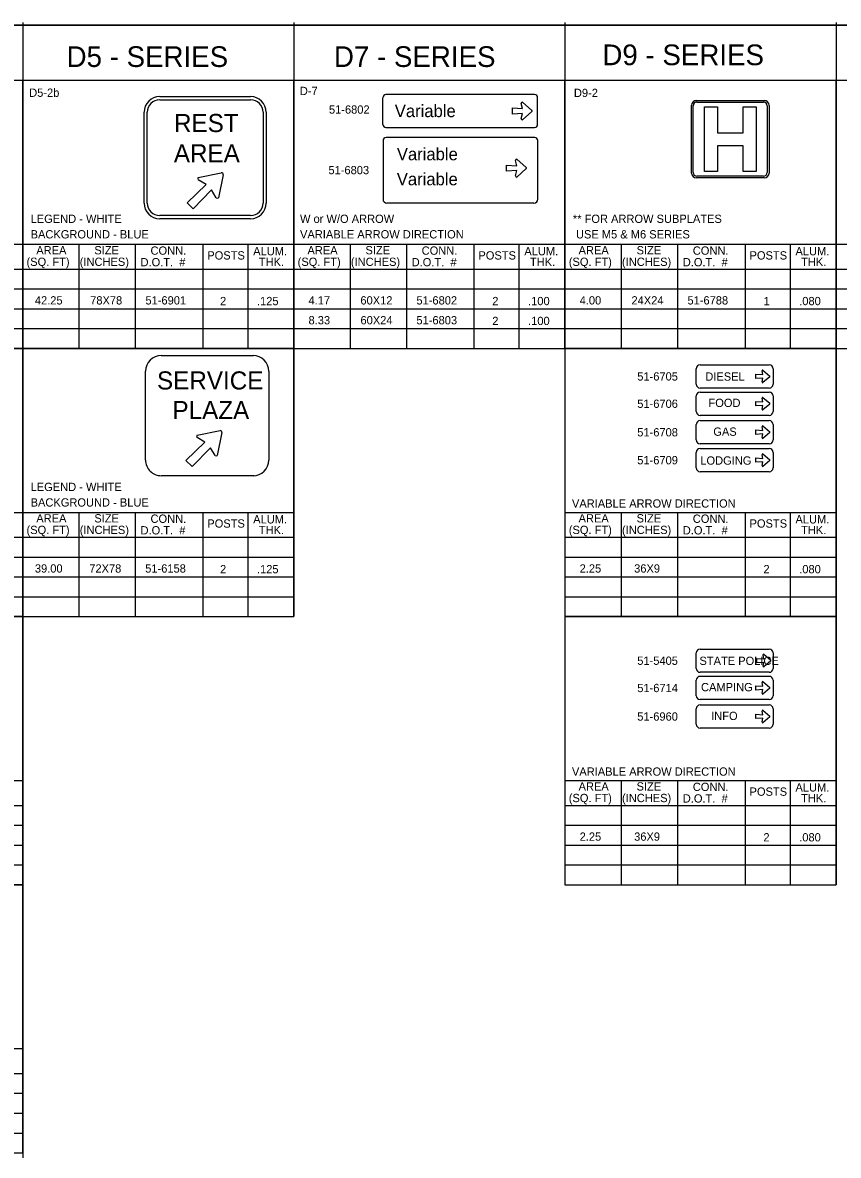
# Model space of a CAD drawing. Extents: x 0 to 2011, y -22 to 1183.
# Drawn here: x 424 to 739.2, y 392.2 to 830 of the extents above; entities that cross this region are included whole.
import ezdxf

# ---------------------------------------------------------------- set-up
doc = ezdxf.new("R2010")
doc.units = 0
for name, color, linetype in [('CT_Border_Perimeter_Shape', 7, 'Continuous'), ('CT_Construction', 7, 'Continuous'), ('Level 1', 7, 'Continuous'), ('Level 2', 7, 'Continuous'), ('Level 22', 7, 'Continuous'), ('Level 5', 7, 'Continuous')]:
    doc.layers.add(name, color=color, linetype=linetype)

msp = doc.modelspace()

# ---------------------------------------------------------------- linework, layer by layer
at = {"layer": 'CT_Border_Perimeter_Shape'}
msp.add_lwpolyline([(0, -0.97), (1270, -0.97), (1270, 829.03), (0, 829.03)], close=True, dxfattribs=at)
at = {"layer": 'CT_Construction'}
msp.add_lwpolyline([(0, 829.03), (1270, 829.03), (1270, 59.03), (0, 59.03)], close=True, dxfattribs=at)
at = {"layer": 'Level 1'}
for p, q in [((477.01, 801.4), (512.09, 801.4)), ((621.79, 802.19), (564.38, 802.19)), ((477.01, 800.19), (512.09, 800.19)), ((563.17, 790.7), (563.17, 800.98)), ((613.22, 794.68), (613.22, 797.08)), ((613.22, 797.08), (617.1, 796.82)), ((617.1, 796.82), (616.59, 798.81)), ((617.1, 799.32), (617.1, 799.32)), ((617.1, 799.32), (620.81, 796.07)), ((623, 790.7), (623, 800.98)), ((470.97, 760.28), (470.97, 795.35)), ((472.18, 760.28), (472.18, 795.35)), ((516.93, 795.35), (516.93, 760.28)), ((518.13, 795.35), (518.13, 760.28)), ((617.1, 794.93), (613.22, 794.68)), ((616.59, 792.94), (617.1, 794.93)), ((617.05, 795.88), (617.05, 795.88)), ((620.81, 795.69), (617.1, 792.43)), ((620.81, 795.69), (620.81, 795.69)), ((564.38, 789.5), (621.79, 789.5)), ((563.26, 784.43), (563.26, 761.76)), ((621.88, 785.64), (564.47, 785.64)), ((623.09, 761.76), (623.09, 784.43)), ((611.03, 772.58), (611.03, 774.98)), ((611.03, 774.98), (614.91, 774.72)), ((614.91, 774.72), (614.4, 776.71)), ((614.91, 777.22), (618.62, 773.97)), ((491.89, 770.15), (500.76, 771.93)), ((501.48, 771.21), (499.71, 762.34)), ((614.91, 772.84), (611.03, 772.58)), ((614.4, 770.85), (614.91, 772.84)), ((618.62, 773.59), (614.91, 770.34)), ((614.91, 773.06), (614.91, 773.06)), ((618.62, 773.59), (618.62, 773.59)), ((487.59, 760.38), (494.89, 767.5)), ((494.89, 767.5), (491.89, 769.29)), ((614.86, 769.61), (614.86, 769.61)), ((497.06, 765.33), (489.94, 758.04)), ((498.84, 762.34), (497.06, 765.33)), ((489.94, 758.04), (487.59, 760.38)), ((621.58, 760.25), (564.77, 760.25)), ((512.09, 755.44), (477.01, 755.44)), ((512.09, 754.23), (477.01, 754.23)), ((512.09, 754.23), (477.01, 754.23)), ((477.54, 701.33), (513.23, 701.33)), ((684.28, 690.28), (684.28, 696.26)), ((685.79, 697.77), (712.45, 697.77)), ((713.96, 696.26), (713.96, 690.28)), ((471.51, 660.95), (471.51, 695.31)), ((471.51, 695.31), (471.51, 695.29)), ((519.13, 695.25), (519.13, 660.95)), ((707.3, 692.45), (707.3, 694.15)), ((707.3, 694.15), (710.05, 693.97)), ((710.05, 692.63), (707.3, 692.45)), ((710.05, 693.97), (709.68, 695.38)), ((709.68, 691.22), (710.05, 692.63)), ((710.05, 695.74), (710.05, 695.74)), ((710.05, 695.74), (712.68, 693.43)), ((712.68, 693.16), (710.05, 690.86)), ((712.68, 693.16), (712.68, 693.16)), ((712.45, 688.77), (685.79, 688.77)), ((684.28, 679.73), (684.28, 685.71)), ((685.79, 687.22), (712.45, 687.22)), ((707.3, 681.9), (707.3, 683.59)), ((707.3, 683.59), (710.05, 683.41)), ((710.05, 683.41), (709.68, 684.82)), ((710.05, 685.19), (710.05, 685.19)), ((710.05, 685.19), (712.68, 682.88)), ((713.96, 685.71), (713.96, 679.73)), ((710.05, 682.08), (707.3, 681.9)), ((709.68, 680.67), (710.05, 682.08)), ((712.68, 682.61), (710.05, 680.3)), ((712.68, 682.61), (712.68, 682.61)), ((684.28, 668.71), (684.28, 674.68)), ((684.28, 668.71), (684.28, 674.68)), ((712.45, 678.22), (685.79, 678.22)), ((685.79, 676.2), (712.45, 676.2)), ((685.79, 676.2), (712.45, 676.2)), ((713.96, 674.68), (713.96, 668.71)), ((713.96, 674.68), (713.96, 668.71)), ((491.42, 670.54), (500.29, 672.31)), ((501.02, 671.59), (499.24, 662.72)), ((707.3, 670.87), (707.3, 672.57)), ((707.3, 672.57), (710.05, 672.39)), ((707.3, 670.87), (707.3, 672.57)), ((707.3, 672.57), (710.05, 672.39)), ((710.05, 671.05), (707.3, 670.87)), ((710.05, 671.05), (707.3, 670.87)), ((710.05, 672.39), (709.68, 673.8)), ((710.05, 672.39), (709.68, 673.8)), ((709.68, 669.64), (710.05, 671.05)), ((709.68, 669.64), (710.05, 671.05)), ((710.05, 674.16), (710.05, 674.16)), ((710.05, 674.16), (712.68, 671.86)), ((710.05, 674.16), (710.05, 674.16)), ((710.05, 674.16), (712.68, 671.86)), ((712.68, 671.59), (710.05, 669.28)), ((712.68, 671.59), (710.05, 669.28)), ((712.68, 671.59), (712.68, 671.59)), ((712.68, 671.59), (712.68, 671.59)), ((487.12, 660.77), (494.42, 667.89)), ((496.59, 665.72), (489.47, 658.42)), ((494.42, 667.89), (491.42, 669.67)), ((498.37, 662.72), (496.59, 665.72)), ((712.45, 667.2), (685.79, 667.2)), ((712.45, 667.2), (685.79, 667.2)), ((684.28, 657.92), (684.28, 663.9)), ((685.79, 665.41), (712.45, 665.41)), ((707.3, 660.09), (707.3, 661.79)), ((707.3, 661.79), (710.05, 661.6)), ((710.05, 661.6), (709.68, 663.02)), ((710.05, 663.38), (710.05, 663.38)), ((710.05, 663.38), (712.68, 661.07)), ((713.96, 663.9), (713.96, 657.92)), ((489.47, 658.42), (487.12, 660.77)), ((710.05, 660.27), (707.3, 660.09)), ((709.68, 658.86), (710.05, 660.27)), ((712.68, 660.8), (710.05, 658.49)), ((712.68, 660.8), (712.68, 660.8)), ((513.49, 654.91), (477.63, 654.91)), ((513.08, 654.91), (477.63, 654.91)), ((712.45, 656.41), (685.79, 656.41)), ((685.79, 587.91), (712.45, 587.91)), ((684.28, 580.42), (684.28, 586.4)), ((707.67, 582.58), (707.67, 584.28)), ((707.67, 584.28), (710.42, 584.1)), ((710.42, 582.77), (707.67, 582.58)), ((710.05, 585.87), (710.05, 585.87)), ((710.42, 584.1), (710.06, 585.51)), ((710.06, 581.35), (710.42, 582.77)), ((710.42, 585.87), (713.05, 583.57)), ((713.05, 583.3), (710.42, 580.99)), ((713.05, 583.3), (713.05, 583.3)), ((713.96, 586.4), (713.96, 580.42)), ((712.45, 578.91), (685.79, 578.91)), ((684.28, 569.87), (684.28, 575.84)), ((685.79, 577.36), (712.45, 577.36)), ((707.3, 572.03), (707.3, 573.73)), ((707.3, 573.73), (710.05, 573.55)), ((710.05, 573.55), (709.68, 574.96)), ((710.05, 575.32), (710.05, 575.32)), ((710.05, 575.32), (712.68, 573.02)), ((713.96, 575.84), (713.96, 569.87)), ((710.05, 572.21), (707.3, 572.03)), ((709.68, 570.8), (710.05, 572.21)), ((712.68, 572.75), (710.05, 570.44)), ((712.68, 572.75), (712.68, 572.75)), ((684.28, 558.85), (684.28, 564.82)), ((684.28, 558.85), (684.28, 564.82)), ((712.45, 568.36), (685.79, 568.36)), ((685.79, 566.33), (712.45, 566.33)), ((685.79, 566.33), (712.45, 566.33)), ((713.96, 564.82), (713.96, 558.85)), ((713.96, 564.82), (713.96, 558.85)), ((707.3, 561.01), (707.3, 562.71)), ((707.3, 562.71), (710.05, 562.53)), ((707.3, 561.01), (707.3, 562.71)), ((707.3, 562.71), (710.05, 562.53)), ((710.05, 561.19), (707.3, 561.01)), ((710.05, 561.19), (707.3, 561.01)), ((710.05, 562.53), (709.68, 563.94)), ((710.05, 562.53), (709.68, 563.94)), ((709.68, 559.78), (710.05, 561.19)), ((709.68, 559.78), (710.05, 561.19)), ((710.05, 564.3), (710.05, 564.3)), ((710.05, 564.3), (712.68, 562)), ((710.05, 564.3), (710.05, 564.3)), ((710.05, 564.3), (712.68, 562)), ((712.68, 561.72), (710.05, 559.42)), ((712.68, 561.72), (710.05, 559.42)), ((712.68, 561.72), (712.68, 561.72)), ((712.68, 561.72), (712.68, 561.72)), ((712.45, 557.34), (685.79, 557.34)), ((712.45, 557.34), (685.79, 557.34))]:
    msp.add_line(p, q, dxfattribs=at)
for centre, radius, start, end in [((477.01, 795.35), 6.05, 90, 180), ((512.09, 795.35), 6.05, 0, 90), ((564.38, 800.98), 1.21, 90, 180), ((621.79, 800.98), 1.21, 360, 90), ((477.01, 795.35), 4.84, 90, 180), ((512.09, 795.35), 4.84, 0, 90), ((617.1, 798.81), 0.51, 90, 180), ((617.1, 792.94), 0.51, 180, 270), ((620.64, 795.88), 0.255, 311.213, 48.6399), ((564.38, 790.7), 1.21, 180, 270), ((621.79, 790.7), 1.21, 270, 0), ((564.47, 784.43), 1.21, 90, 180), ((621.88, 784.43), 1.21, 360, 90), ((614.91, 776.71), 0.51, 90, 180), ((500.88, 771.33), 0.614, 348.709, 101.2855), ((614.91, 770.85), 0.51, 180, 270), ((618.45, 773.78), 0.255, 311.213, 48.6399), ((492.33, 769.72), 0.614, 135, 225), ((499.28, 762.77), 0.614, 225, 315), ((564.77, 761.76), 1.51, 180, 270), ((621.58, 761.76), 1.51, 270, 360), ((477.01, 760.28), 6.05, 180, 270), ((477.01, 760.28), 4.84, 180, 270), ((512.09, 760.28), 6.05, 270, 360), ((512.09, 760.28), 4.84, 270, 360), ((477.56, 695.29), 6.05, 90, 180), ((513.08, 695.29), 6.05, 0, 90), ((685.79, 696.26), 1.51, 90, 180), ((712.45, 696.26), 1.51, 360, 90), ((710.05, 695.38), 0.362, 90, 180), ((712.56, 693.3), 0.181, 311.213, 48.6399), ((685.79, 690.28), 1.51, 180, 270), ((710.05, 691.22), 0.362, 180, 270), ((712.45, 690.28), 1.51, 270, 360), ((685.79, 685.71), 1.51, 90, 180), ((710.05, 684.82), 0.362, 90, 180), ((712.45, 685.71), 1.51, 360, 90), ((685.79, 679.73), 1.51, 180, 270), ((710.05, 680.67), 0.362, 180, 270), ((712.45, 679.73), 1.51, 270, 0), ((712.56, 682.75), 0.181, 311.213, 48.6399), ((685.79, 674.68), 1.51, 90, 180), ((685.79, 674.68), 1.51, 90, 180), ((712.45, 674.68), 1.51, 0, 90), ((712.45, 674.68), 1.51, 360, 90), ((491.86, 670.11), 0.614, 135, 225), ((500.41, 671.71), 0.614, 348.709, 101.2855), ((710.05, 673.8), 0.362, 90, 180), ((710.05, 673.8), 0.362, 90, 180), ((712.56, 671.72), 0.181, 311.213, 48.6399), ((712.56, 671.72), 0.181, 311.213, 48.6399), ((685.79, 668.71), 1.51, 180, 270), ((685.79, 668.71), 1.51, 180, 270), ((710.05, 669.64), 0.362, 180, 270), ((710.05, 669.64), 0.362, 180, 270), ((712.45, 668.71), 1.51, 270, 360), ((712.45, 668.71), 1.51, 270, 0), ((498.81, 663.16), 0.614, 225, 315), ((685.79, 663.9), 1.51, 90, 180), ((710.05, 663.02), 0.362, 90, 180), ((712.45, 663.9), 1.51, 0, 90), ((712.56, 660.94), 0.181, 311.213, 48.6399), ((477.56, 660.95), 6.05, 180, 270.6543), ((513.08, 660.95), 6.05, 270, 360), ((685.79, 657.92), 1.51, 180, 270), ((710.05, 658.86), 0.362, 180, 270), ((712.45, 657.92), 1.51, 270, 360), ((685.79, 586.4), 1.51, 90, 180), ((712.45, 586.4), 1.51, 360, 90), ((710.42, 585.51), 0.362, 90, 180), ((712.93, 583.43), 0.181, 311.213, 48.6399), ((685.79, 580.42), 1.51, 180, 270), ((710.42, 581.36), 0.362, 180, 270), ((712.45, 580.42), 1.51, 270, 360), ((685.79, 575.84), 1.51, 90, 180), ((710.05, 574.96), 0.362, 90, 180), ((712.45, 575.84), 1.51, 360, 90), ((685.79, 569.87), 1.51, 180, 270), ((710.05, 570.8), 0.362, 180, 270), ((712.45, 569.87), 1.51, 270, 0), ((712.56, 572.88), 0.181, 311.213, 48.6399), ((685.79, 564.82), 1.51, 90, 180), ((685.79, 564.82), 1.51, 90, 180), ((712.45, 564.82), 1.51, 0, 90), ((712.45, 564.82), 1.51, 360, 90), ((710.05, 563.94), 0.362, 90, 180), ((710.05, 563.94), 0.362, 90, 180), ((712.56, 561.86), 0.181, 311.213, 48.6399), ((712.56, 561.86), 0.181, 311.213, 48.6399), ((685.79, 558.85), 1.51, 180, 270), ((685.79, 558.85), 1.51, 180, 270), ((710.05, 559.78), 0.362, 180, 270), ((710.05, 559.78), 0.362, 180, 270), ((712.45, 558.85), 1.51, 270, 360), ((712.45, 558.85), 1.51, 270, 0)]:
    msp.add_arc(centre, radius, start, end, dxfattribs=at)
at = {"layer": 'Level 2'}
for p, q in [((319.3, 744.34), (424.05, 744.34)), ((424.05, 744.34), (528.79, 744.34)), ((445.8, 744.34), (445.8, 704.06)), ((467.55, 744.34), (467.55, 704.06)), ((493.65, 744.34), (493.65, 704.06)), ((511.05, 744.34), (511.05, 704.06)), ((528.79, 744.34), (633.54, 744.34)), ((550.54, 744.34), (550.54, 704.06)), ((572.29, 744.34), (572.29, 704.06)), ((598.39, 744.34), (598.39, 704.06)), ((615.79, 744.34), (615.79, 704.06)), ((633.54, 744.34), (738.29, 744.34)), ((655.29, 744.34), (655.29, 704.06)), ((677.04, 744.34), (677.04, 704.06)), ((703.14, 744.34), (703.14, 704.06)), ((720.54, 744.34), (720.54, 704.06)), ((738.29, 744.34), (843.04, 744.34)), ((319.3, 734.75), (424.05, 734.75)), ((424.05, 734.75), (528.79, 734.75)), ((528.79, 734.75), (633.54, 734.75)), ((633.54, 734.75), (738.29, 734.75)), ((738.29, 734.75), (843.04, 734.75)), ((319.3, 727.07), (424.05, 727.07)), ((424.05, 727.07), (528.79, 727.07)), ((528.79, 727.07), (633.54, 727.07)), ((633.54, 727.07), (738.29, 727.07)), ((738.29, 727.07), (843.04, 727.07)), ((319.3, 719.4), (424.05, 719.4)), ((424.05, 719.4), (528.79, 719.4)), ((528.79, 719.4), (633.54, 719.4)), ((633.54, 719.4), (738.29, 719.4)), ((738.29, 719.4), (843.04, 719.4)), ((319.3, 711.73), (424.05, 711.73)), ((424.05, 711.73), (528.79, 711.73)), ((528.79, 711.73), (633.54, 711.73)), ((633.54, 711.73), (738.29, 711.73)), ((738.29, 711.73), (843.04, 711.73)), ((319.3, 640.71), (424.05, 640.71)), ((424.05, 640.71), (528.79, 640.71)), ((445.8, 640.71), (445.8, 600.44)), ((467.55, 640.71), (467.55, 600.44)), ((493.65, 640.71), (493.65, 600.44)), ((511.05, 640.71), (511.05, 600.44)), ((633.54, 640.71), (738.29, 640.71)), ((655.29, 640.71), (655.29, 600.44)), ((677.04, 640.71), (677.04, 600.44)), ((703.14, 640.71), (703.14, 600.44)), ((720.54, 640.71), (720.54, 600.44)), ((319.3, 631.12), (424.05, 631.12)), ((424.05, 631.12), (528.79, 631.12)), ((633.54, 631.12), (738.29, 631.12)), ((319.3, 623.45), (424.05, 623.45)), ((424.05, 623.45), (528.79, 623.45)), ((633.54, 623.45), (738.29, 623.45)), ((319.3, 615.78), (424.05, 615.78)), ((424.05, 615.78), (528.79, 615.78)), ((633.54, 615.78), (738.29, 615.78)), ((319.3, 608.11), (424.05, 608.11)), ((424.05, 608.11), (528.79, 608.11)), ((633.54, 608.11), (738.29, 608.11)), ((319.3, 537.09), (424.05, 537.09)), ((633.54, 537.09), (738.29, 537.09)), ((655.29, 537.09), (655.29, 496.81)), ((677.04, 537.09), (677.04, 496.81)), ((703.14, 537.09), (703.14, 496.81)), ((720.54, 537.09), (720.54, 496.81)), ((319.3, 527.5), (424.05, 527.5)), ((633.54, 527.5), (738.29, 527.5)), ((319.3, 519.83), (424.05, 519.83)), ((633.54, 519.83), (738.29, 519.83)), ((319.3, 512.16), (424.05, 512.16)), ((633.54, 512.16), (738.29, 512.16)), ((319.3, 504.48), (424.05, 504.48)), ((633.54, 504.48), (738.29, 504.48)), ((319.3, 433.47), (424.05, 433.47)), ((319.3, 423.88), (424.05, 423.88)), ((319.3, 416.2), (424.05, 416.2)), ((319.3, 408.53), (424.05, 408.53)), ((319.3, 400.86), (424.05, 400.86))]:
    msp.add_line(p, q, dxfattribs=at)
for points in [[(424.05, 807.68), (319.3, 807.68), (319.3, 704.06), (424.05, 704.06)], [(528.79, 807.68), (424.05, 807.68), (424.05, 704.06), (528.79, 704.06)], [(633.54, 807.68), (528.79, 807.68), (528.79, 704.06), (633.54, 704.06)], [(738.29, 807.68), (633.54, 807.68), (633.54, 704.06), (738.29, 704.06)], [(843.04, 807.68), (738.29, 807.68), (738.29, 704.06), (843.04, 704.06)], [(424.05, 704.06), (319.3, 704.06), (319.3, 600.44), (424.05, 600.44)], [(528.79, 704.06), (424.05, 704.06), (424.05, 600.44), (528.79, 600.44)], [(738.29, 704.06), (633.54, 704.06), (633.54, 600.44), (738.29, 600.44)], [(424.05, 600.44), (319.3, 600.44), (319.3, 496.81), (424.05, 496.81)], [(738.29, 600.44), (633.54, 600.44), (633.54, 496.81), (738.29, 496.81)], [(424.05, 496.81), (319.3, 496.81), (319.3, 393.19), (424.05, 393.19)]]:
    msp.add_lwpolyline(points, close=True, dxfattribs=at)
at = {"layer": 'Level 22'}
for p, q in [((682.47, 771.85), (682.47, 798.04)), ((683.11, 772.1), (683.11, 797.91)), ((684.34, 799.91), (710.53, 799.91)), ((684.52, 799.33), (710.27, 799.33)), ((687.45, 772.48), (687.45, 797.42)), ((687.45, 797.42), (692.44, 797.42)), ((692.44, 797.42), (692.44, 787.44)), ((702.42, 787.44), (702.42, 797.42)), ((702.42, 797.42), (707.41, 797.42)), ((707.41, 797.42), (707.41, 772.48)), ((711.69, 797.91), (711.69, 772.1)), ((712.4, 798.04), (712.4, 771.85)), ((692.44, 787.44), (702.42, 787.44)), ((702.42, 782.45), (692.44, 782.45)), ((692.44, 782.45), (692.44, 772.48)), ((702.42, 772.48), (702.42, 782.45)), ((710.27, 770.68), (684.52, 770.68)), ((692.44, 772.48), (687.45, 772.48)), ((707.41, 772.48), (702.42, 772.48)), ((710.53, 769.98), (684.34, 769.98))]:
    msp.add_line(p, q, dxfattribs=at)
for centre, radius, start, end in [((684.34, 798.04), 1.87, 90, 180), ((684.52, 797.91), 1.42, 90, 180), ((710.27, 797.91), 1.42, 360, 90), ((710.53, 798.04), 1.87, 360, 90), ((684.34, 771.85), 1.87, 180, 270), ((684.52, 772.1), 1.42, 180, 270), ((710.27, 772.1), 1.42, 270, 0), ((710.53, 771.85), 1.87, 270, 0)]:
    msp.add_arc(centre, radius, start, end, dxfattribs=at)
at = {"layer": 'Level 5'}
for p, q in [((424.05, 830), (424.05, 391.26)), ((528.79, 830), (528.79, 600.44)), ((633.54, 830), (633.54, 496.81)), ((738.29, 830), (738.29, 496.81))]:
    msp.add_line(p, q, dxfattribs=at)

# ---------------------------------------------------------------- texts
at = {"layer": 'Level 1'}
for s, p in [('D5 - SERIES', (441.01, 812.87)), ('D7 - SERIES', (544.3, 812.87)), ('D9 - SERIES', (648.01, 813.56))]:
    msp.add_text(s, height=8, dxfattribs=at).set_placement(p)
at = {"layer": 'Level 2'}
for s, height, p in [('D5-2b', 3.2, (426.56, 801.33)), ('D-7', 3.2, (531.13, 802.01)), ('D9-2', 3.2, (637.01, 801.25)), ('51-6802', 3.2, (542.37, 794.82)), ('Variable', 4.8, (567.81, 793.48)), ('REST', 7, (482.51, 787.71)), ('AREA', 7, (482.45, 776)), ('Variable', 4.8, (568.61, 776.81)), ('51-6803', 3.2, (542.18, 771.42)), ('Variable', 4.8, (568.59, 767.14)), ('LEGEND - WHITE', 3.2, (427.12, 752.6)), ('W or W/O ARROW', 3.2, (531.2, 752.6)), ('** FOR ARROW SUBPLATES', 3.2, (636.62, 752.6)), ('BACKGROUND - BLUE', 3.2, (427.12, 746.6)), ('VARIABLE ARROW DIRECTION', 3.2, (531.2, 746.6)), (' USE M5 & M6 SERIES', 3.2, (636.62, 746.6)), ('AREA', 3.2, (429.31, 740.45)), ('SIZE', 3.2, (451.73, 740.45)), ('CONN.', 3.2, (473.44, 740.3)), ('POSTS', 3.2, (495.37, 738.45)), ('ALUM.', 3.2, (513.11, 740.07)), ('AREA', 3.2, (534.06, 740.45)), ('SIZE', 3.2, (556.47, 740.45)), ('CONN.', 3.2, (578.19, 740.3)), ('POSTS', 3.2, (600.12, 738.45)), ('ALUM.', 3.2, (617.86, 740.07)), ('AREA', 3.2, (638.81, 740.45)), ('SIZE', 3.2, (661.22, 740.45)), ('CONN.', 3.2, (682.94, 740.3)), ('POSTS', 3.2, (704.86, 738.45)), ('ALUM.', 3.2, (722.6, 740.07)), ('(SQ. FT)', 3.2, (425.53, 735.98)), ('(INCHES)', 3.2, (446.1, 735.98)), ('D.O.T.  #', 3.2, (469.58, 735.83)), ('THK.', 3.2, (515.29, 735.93)), ('(SQ. FT)', 3.2, (530.28, 735.98)), ('(INCHES)', 3.2, (550.84, 735.98)), ('D.O.T.  #', 3.2, (574.33, 735.83)), ('THK.', 3.2, (620.03, 735.93)), ('(SQ. FT)', 3.2, (635.03, 735.98)), ('(INCHES)', 3.2, (655.59, 735.98)), ('D.O.T.  #', 3.2, (679.07, 735.83)), ('THK.', 3.2, (724.78, 735.93)), ('SERVICE', 7, (475.95, 688.22)), ('51-6705', 3.2, (661.48, 691.67)), ('DIESEL', 3.2, (687.77, 691.62)), ('PLAZA', 7, (481.93, 676.76)), ('51-6706', 3.2, (661.48, 681.11)), ('FOOD', 3.2, (689, 681.45)), ('51-6708', 3.2, (661.48, 670.09)), ('GAS', 3.2, (690.86, 670.33)), ('51-6709', 3.2, (661.48, 659.3)), ('LODGING', 3.2, (685.85, 659.16)), ('LEGEND - WHITE', 3.2, (427.12, 648.97)), ('BACKGROUND - BLUE', 3.2, (427.12, 642.97)), ('VARIABLE ARROW DIRECTION', 3.2, (636.25, 642.57)), ('AREA', 3.2, (429.31, 636.83)), ('SIZE', 3.2, (451.73, 636.83)), ('CONN.', 3.2, (473.44, 636.68)), ('ALUM.', 3.2, (513.11, 636.45)), ('AREA', 3.2, (638.81, 636.83)), ('SIZE', 3.2, (661.22, 636.83)), ('CONN.', 3.2, (682.94, 636.68)), ('ALUM.', 3.2, (722.6, 636.45)), ('(SQ. FT)', 3.2, (425.53, 632.36)), ('(INCHES)', 3.2, (446.1, 632.36)), ('D.O.T.  #', 3.2, (469.58, 632.2)), ('POSTS', 3.2, (495.37, 634.83)), ('THK.', 3.2, (515.29, 632.31)), ('(SQ. FT)', 3.2, (635.03, 632.36)), ('(INCHES)', 3.2, (655.59, 632.36)), ('D.O.T.  #', 3.2, (679.07, 632.2)), ('POSTS', 3.2, (704.86, 634.83)), ('THK.', 3.2, (724.78, 632.31)), ('51-5405', 3.2, (661.48, 581.8)), ('STATE POLICE', 3.2, (685.51, 581.76)), ('51-6714', 3.2, (661.48, 571.25)), ('CAMPING', 3.2, (686.12, 571.59)), ('51-6960', 3.2, (661.48, 560.23)), ('INFO', 3.2, (690.03, 560.47)), ('VARIABLE ARROW DIRECTION', 3.2, (636.25, 538.95)), ('AREA', 3.2, (638.81, 533.21)), ('SIZE', 3.2, (661.22, 533.21)), ('CONN.', 3.2, (682.94, 533.05)), ('POSTS', 3.2, (704.86, 531.2)), ('ALUM.', 3.2, (722.6, 532.83)), ('(SQ. FT)', 3.2, (635.03, 528.74)), ('(INCHES)', 3.2, (655.59, 528.74)), ('D.O.T.  #', 3.2, (679.07, 528.58)), ('THK.', 3.2, (724.78, 528.69))]:
    msp.add_text(s, height=height, dxfattribs=at).set_placement(p)
at = {"layer": 'Level 5'}
for s, p in [('42.25', (428.76, 721.07)), ('78X78', (450.13, 721.07)), ('51-6901', (471.48, 721.07)), (' 2', (499.12, 720.8)), ('.125', (514.57, 720.8)), (' 4.17', (533.29, 721.07)), ('60X12', (554.53, 721.07)), ('51-6802', (576.17, 721.07)), ('2', (605.47, 720.8)), ('.100', (619.31, 720.8)), (' 4.00', (638.04, 721.07)), ('24X24', (659.25, 721.07)), ('51-6788', (680.88, 721.07)), ('1', (710.28, 720.8)), ('.080', (724.06, 720.8)), (' 8.33', (533.29, 713.4)), ('60X24', (554.56, 713.4)), ('51-6803', (576.17, 713.4)), ('2', (605.47, 713.13)), ('.100', (619.31, 713.13)), ('39.00', (428.76, 617.45)), ('72X78', (449.78, 617.45)), ('51-6158', (471.39, 617.45)), (' 2', (499.12, 617.18)), ('.125', (514.57, 617.18)), (' 2.25', (638.04, 617.45)), (' 36X9', (659.09, 617.45)), ('2', (710.22, 617.18)), ('.080', (724.06, 617.18)), (' 2.25', (638.04, 513.82)), (' 36X9', (659.09, 513.82)), ('2', (710.22, 513.56)), ('.080', (724.06, 513.56))]:
    msp.add_text(s, height=3.2, dxfattribs=at).set_placement(p)

doc.saveas('drawing.dxf')
